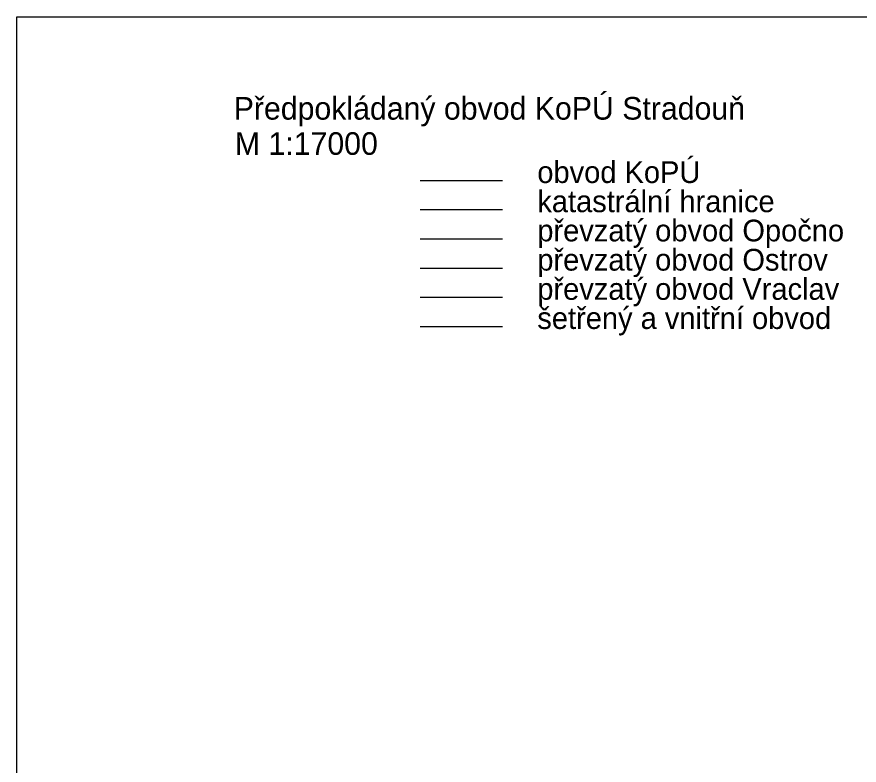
# Model space of a CAD drawing. Extents: x -629983 to -626385, y -1072828 to -1067897.
# Drawn here: x -629983 to -628121, y -1069550 to -1067897 of the extents above; entities that cross this region are included whole.
import ezdxf

# ---------------------------------------------------------------- set-up
doc = ezdxf.new("R2010")
doc.units = 0
for name, color, linetype in [('Default', 7, 'Continuous'), ('Katastrální hranice', 7, 'Continuous'), ('Převzatý obvod_Opočno', 7, 'Continuous'), ('Převzatý obvod_Ostrov', 7, 'Continuous'), ('Převzatý obvod_Vraclav', 7, 'Continuous'), ('Šetřený obvod', 7, 'Continuous')]:
    doc.layers.add(name, color=color, linetype=linetype)

msp = doc.modelspace()

# ---------------------------------------------------------------- linework, layer by layer
at = {"layer": 'Default'}
msp.add_lwpolyline([(-629982.6, -1067896.7), (-626385, -1067896.7), (-626385, -1072827.9), (-629982.6, -1072827.9)], close=True, dxfattribs=at)
at = {"layer": 'Katastrální hranice'}
for p, q in [((-629091.1, -1068258.2), (-628909.7, -1068258.2)), ((-629091.1, -1068322.7), (-628909.7, -1068322.7)), ((-629091.1, -1068387.3), (-628909.7, -1068387.3)), ((-629091.1, -1068451.8), (-628909.7, -1068451.8)), ((-629091.1, -1068516.3), (-628909.7, -1068516.3)), ((-629091.1, -1068580.8), (-628909.7, -1068580.8))]:
    msp.add_line(p, q, dxfattribs=at)

# ---------------------------------------------------------------- texts
at = {"layer": 'Default'}
for s, height, p in [('Předpokládaný obvod KoPÚ Stradouň', 50, (-629503.4, -1068123.9)), ('M 1:17000', 50, (-629500.8, -1068201.7)), ('obvod KoPÚ', 48, (-628832.4, -1068263.9)), ('katastrální hranice', 48, (-628832.4, -1068328.4))]:
    msp.add_text(s, height=height, dxfattribs=at).set_placement(p)
at = {"layer": 'Převzatý obvod_Opočno'}
msp.add_text('převzatý obvod Opočno', height=48, dxfattribs=at).set_placement((-628832.4, -1068392.9))
at = {"layer": 'Převzatý obvod_Ostrov'}
msp.add_text('převzatý obvod Ostrov', height=48, dxfattribs=at).set_placement((-628832.4, -1068457.5))
at = {"layer": 'Převzatý obvod_Vraclav'}
msp.add_text('převzatý obvod Vraclav', height=48, dxfattribs=at).set_placement((-628832.4, -1068522))
at = {"layer": 'Šetřený obvod'}
msp.add_text('šetřený a vnitřní obvod', height=48, dxfattribs=at).set_placement((-628832.4, -1068586.5))

doc.saveas('drawing.dxf')
